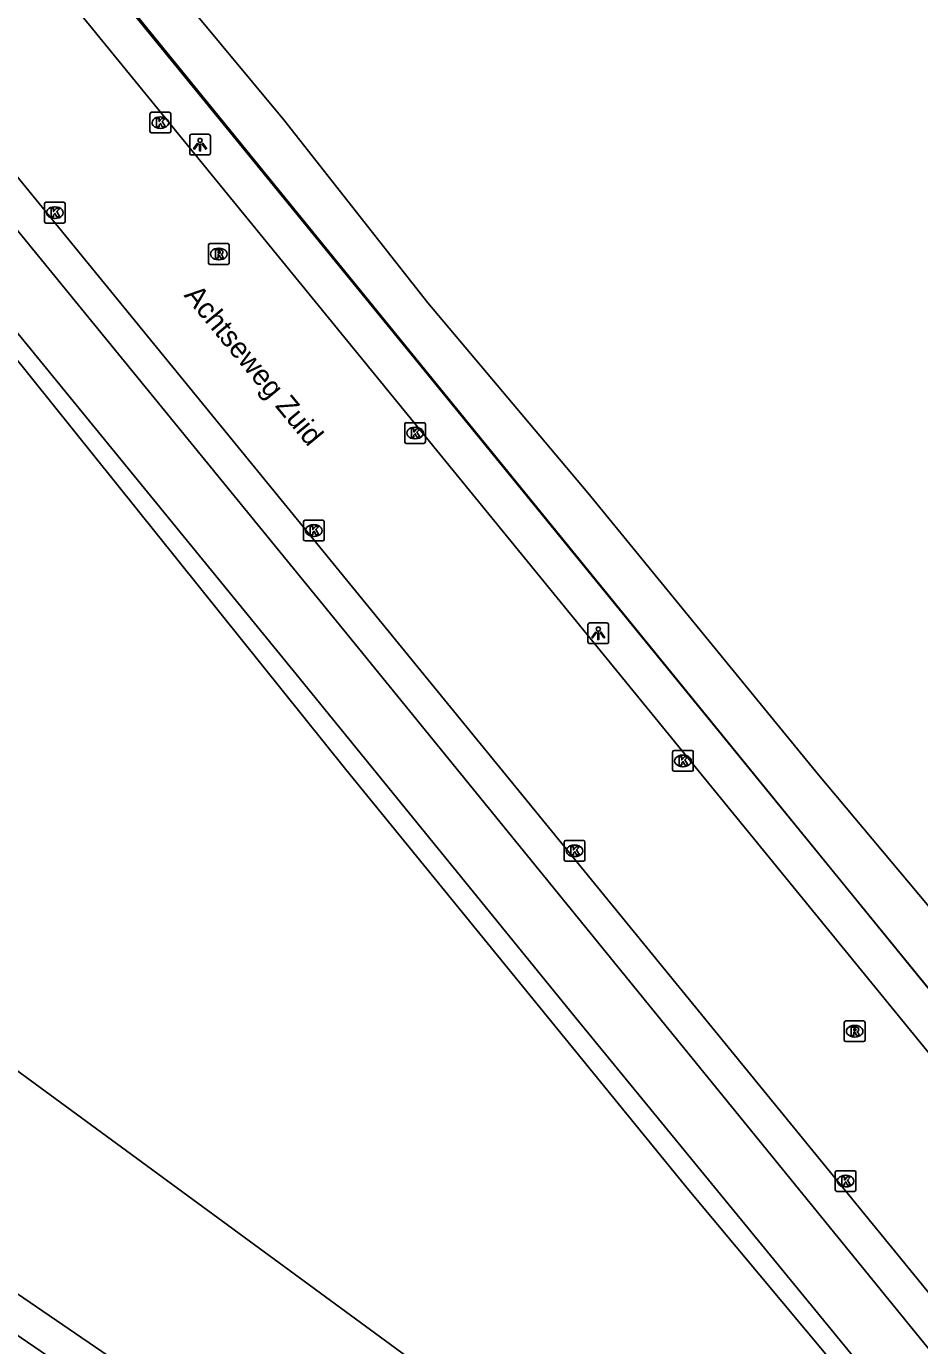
# Model space of a CAD drawing. Extents: x 157154 to 159278, y 385000 to 386650.
# Drawn here: x 158566.6 to 158609.7, y 386048.4 to 386112.1 of the extents above; entities that cross this region are included whole.
import ezdxf

# ---------------------------------------------------------------- set-up
doc = ezdxf.new("R2010")
doc.units = 0
for name, color, linetype in [('IMGEO_Berm_groen', 7, 'Continuous'), ('IMGEO_Fietspad_gesloten', 7, 'Continuous'), ('IMGEO_Gemengd_bos', 7, 'Continuous'), ('IMGEO_Hek', 7, 'Continuous'), ('IMGEO_Kolk', 7, 'Continuous'), ('IMGEO_Lichtpunt', 7, 'Continuous'), ('IMGEO_Openbare_ruimte_label', 7, 'Continuous'), ('IMGEO_Rijbaan_lokaal_open', 7, 'Continuous'), ('IMGEO_Rioolput', 7, 'Continuous'), ('IMGEO_Spoorbaan_halfverhard', 7, 'Continuous')]:
    doc.layers.add(name, color=color, linetype=linetype)

msp = doc.modelspace()

# ---------------------------------------------------------------- linework, layer by layer
at = {"layer": 'IMGEO_Berm_groen'}
msp.add_lwpolyline([(158841.489, 385782.337), (158835.15, 385790.114), (158809.757, 385821.269), (158676.254, 385984.739), (158663.791, 386000), (158641.091, 386027.796), (158568.335, 386116.93)], dxfattribs=at)
at = {"layer": 'IMGEO_Fietspad_gesloten'}
for points in [[(158496.283, 386187.658), (158499.727, 386183.447), (158522.187, 386156.142), (158552.142, 386119.431), (158582.074, 386082.79), (158611.265, 386046.941), (158624.352, 386030.949), (158632.65, 386020.898), (158649.904, 386000), (158653.358, 385995.817), (158682.792, 385959.807), (158711.087, 385925.065), (158740.719, 385888.815), (158770.311, 385852.497), (158799.749, 385816.443), (158822.714, 385788.211), (158826.18, 385783.962)], [(158827.277, 385777.76), (158822.455, 385783.643), (158820.309, 385786.377), (158797.347, 385814.415), (158767.845, 385850.525), (158738.269, 385886.799), (158708.596, 385923.166), (158680.309, 385957.863), (158650.869, 385993.846), (158645.822, 386000), (158630.32, 386018.902), (158593.245, 386064.109), (158579.638, 386080.846), (158549.77, 386117.391), (158519.812, 386154.179), (158500, 386178.402), (158498.839, 386179.679), (158494.054, 386185.565)]]:
    msp.add_lwpolyline(points, dxfattribs=at)
at = {"layer": 'IMGEO_Gemengd_bos'}
for points in [[(158522.421, 386148.754), (158522.797, 386149.273), (158562.792, 386100.195), (158582.034, 386076.24), (158598.59, 386055.948), (158614.423, 386036.988), (158629.667, 386018.342), (158644.664, 386000), (158685.906, 385949.871), (158806.779, 385801.489), (158826.26, 385777.342), (158807.778, 385750), (158754.904, 385671.741), (158747.524, 385671.524)], [(158752.088, 385863.94), (158673.395, 385918.963), (158680.465, 385942.644), (158609.969, 386004.227), (158617.585, 386024.002), (158504.436, 386106.963), (158449.164, 386031.579), (158559.121, 385955.588)]]:
    msp.add_lwpolyline(points, dxfattribs=at)
at = {"layer": 'IMGEO_Hek'}
for points in [[(158629.667, 386018.342), (158614.423, 386036.988), (158598.59, 386055.948), (158582.034, 386076.24), (158562.792, 386100.195), (158522.797, 386149.273), (158522.421, 386148.754)], [(158817.976, 385811.106), (158808.477, 385822.704), (158800.605, 385832.374), (158792.744, 385842.021), (158789.55, 385845.893), (158757.964, 385884.486), (158738.986, 385907.741), (158732.747, 385915.407), (158728.03, 385921.204), (158723.262, 385926.998), (158694.914, 385961.78), (158690.262, 385967.581), (158687.052, 385971.435), (158669.656, 385992.715), (158661.796, 386002.376), (158660.21, 386004.291), (158633.403, 386037.186), (158611.324, 386064.219), (158568.401, 386116.979)]]:
    msp.add_lwpolyline(points, dxfattribs=at)
at = {"layer": 'IMGEO_Kolk'}
for p, q in [((158572.577, 386107.031), (158572.577, 386107.883)), ((158572.652, 386107.957), (158573.504, 386107.957)), ((158573.065, 386107.737), (158573.09, 386107.737)), ((158573.578, 386107.883), (158573.578, 386107.031)), ((158573.504, 386106.957), (158572.652, 386106.957)), ((158573.088, 386107.177), (158573.063, 386107.177)), ((158567.481, 386102.687), (158567.481, 386103.539)), ((158567.556, 386103.613), (158568.408, 386103.613)), ((158567.969, 386103.393), (158567.994, 386103.393)), ((158568.482, 386103.539), (158568.482, 386102.687)), ((158568.408, 386102.613), (158567.556, 386102.613)), ((158567.992, 386102.833), (158567.967, 386102.833)), ((158584.948, 386092.978), (158585.8, 386092.978)), ((158584.873, 386092.052), (158584.873, 386092.904)), ((158585.361, 386092.758), (158585.386, 386092.758)), ((158585.874, 386092.904), (158585.874, 386092.052)), ((158585.8, 386091.978), (158584.948, 386091.978)), ((158585.384, 386092.198), (158585.359, 386092.198)), ((158579.987, 386087.345), (158579.987, 386088.197)), ((158580.062, 386088.271), (158580.914, 386088.271)), ((158580.475, 386088.051), (158580.5, 386088.051)), ((158580.988, 386088.197), (158580.988, 386087.345)), ((158580.914, 386087.271), (158580.062, 386087.271)), ((158580.498, 386087.491), (158580.473, 386087.491)), ((158597.804, 386076.231), (158597.804, 386077.083)), ((158597.879, 386077.157), (158598.731, 386077.157)), ((158598.805, 386077.083), (158598.805, 386076.231)), ((158598.292, 386076.937), (158598.317, 386076.937)), ((158598.731, 386076.157), (158597.879, 386076.157)), ((158598.315, 386076.377), (158598.29, 386076.377)), ((158592.572, 386071.89), (158592.572, 386072.742)), ((158592.647, 386072.816), (158593.499, 386072.816)), ((158593.06, 386072.596), (158593.085, 386072.596)), ((158593.573, 386072.742), (158593.573, 386071.89)), ((158593.083, 386072.036), (158593.058, 386072.036)), ((158593.499, 386071.816), (158592.647, 386071.816)), ((158605.655, 386055.955), (158605.655, 386056.807)), ((158605.73, 386056.881), (158606.582, 386056.881)), ((158606.143, 386056.661), (158606.168, 386056.661)), ((158606.656, 386056.807), (158606.656, 386055.955)), ((158606.166, 386056.101), (158606.141, 386056.101)), ((158606.582, 386055.881), (158605.73, 386055.881))]:
    msp.add_line(p, q, dxfattribs=at)
for points in [[(158572.577, 386107.031), (158572.577, 386107.883)], [(158572.652, 386107.957), (158573.504, 386107.957)], [(158572.898, 386107.657), (158573.021, 386107.657), (158573.021, 386107.506), (158573.151, 386107.657), (158573.315, 386107.657), (158573.169, 386107.506), (158573.322, 386107.257), (158573.17, 386107.257), (158573.085, 386107.421), (158573.021, 386107.354), (158573.021, 386107.257), (158572.898, 386107.257), (158572.898, 386107.657)], [(158573.578, 386107.883), (158573.578, 386107.031)], [(158573.504, 386106.957), (158572.652, 386106.957)], [(158567.481, 386102.687), (158567.481, 386103.539)], [(158567.556, 386103.613), (158568.408, 386103.613)], [(158567.802, 386103.313), (158567.925, 386103.313), (158567.925, 386103.162), (158568.055, 386103.313), (158568.219, 386103.313), (158568.073, 386103.162), (158568.226, 386102.913), (158568.074, 386102.913), (158567.989, 386103.077), (158567.925, 386103.01), (158567.925, 386102.913), (158567.802, 386102.913), (158567.802, 386103.313)], [(158568.482, 386103.539), (158568.482, 386102.687)], [(158568.408, 386102.613), (158567.556, 386102.613)], [(158584.948, 386092.978), (158585.8, 386092.978)], [(158584.873, 386092.052), (158584.873, 386092.904)], [(158585.194, 386092.678), (158585.317, 386092.678), (158585.317, 386092.527), (158585.447, 386092.678), (158585.611, 386092.678), (158585.465, 386092.527), (158585.618, 386092.278), (158585.466, 386092.278), (158585.381, 386092.442), (158585.317, 386092.375), (158585.317, 386092.278), (158585.194, 386092.278), (158585.194, 386092.678)], [(158585.874, 386092.904), (158585.874, 386092.052)], [(158585.8, 386091.978), (158584.948, 386091.978)], [(158579.987, 386087.345), (158579.987, 386088.197)], [(158580.062, 386088.271), (158580.914, 386088.271)], [(158580.308, 386087.971), (158580.431, 386087.971), (158580.431, 386087.82), (158580.561, 386087.971), (158580.725, 386087.971), (158580.579, 386087.82), (158580.732, 386087.571), (158580.58, 386087.571), (158580.495, 386087.735), (158580.431, 386087.668), (158580.431, 386087.571), (158580.308, 386087.571), (158580.308, 386087.971)], [(158580.988, 386088.197), (158580.988, 386087.345)], [(158580.914, 386087.271), (158580.062, 386087.271)], [(158597.804, 386076.231), (158597.804, 386077.083)], [(158597.879, 386077.157), (158598.731, 386077.157)], [(158598.805, 386077.083), (158598.805, 386076.231)], [(158598.125, 386076.857), (158598.248, 386076.857), (158598.248, 386076.706), (158598.378, 386076.857), (158598.542, 386076.857), (158598.396, 386076.706), (158598.549, 386076.457), (158598.397, 386076.457), (158598.312, 386076.621), (158598.248, 386076.554), (158598.248, 386076.457), (158598.125, 386076.457), (158598.125, 386076.857)], [(158598.731, 386076.157), (158597.879, 386076.157)], [(158592.572, 386071.89), (158592.572, 386072.742)], [(158592.647, 386072.816), (158593.499, 386072.816)], [(158593.573, 386072.742), (158593.573, 386071.89)], [(158592.893, 386072.516), (158593.016, 386072.516), (158593.016, 386072.365), (158593.146, 386072.516), (158593.31, 386072.516), (158593.164, 386072.365), (158593.317, 386072.116), (158593.165, 386072.116), (158593.08, 386072.28), (158593.016, 386072.213), (158593.016, 386072.116), (158592.893, 386072.116), (158592.893, 386072.516)], [(158593.499, 386071.816), (158592.647, 386071.816)], [(158605.655, 386055.955), (158605.655, 386056.807)], [(158605.73, 386056.881), (158606.582, 386056.881)], [(158606.656, 386056.807), (158606.656, 386055.955)], [(158605.976, 386056.581), (158606.099, 386056.581), (158606.099, 386056.43), (158606.229, 386056.581), (158606.393, 386056.581), (158606.247, 386056.43), (158606.4, 386056.181), (158606.248, 386056.181), (158606.163, 386056.345), (158606.099, 386056.278), (158606.099, 386056.181), (158605.976, 386056.181), (158605.976, 386056.581)], [(158606.582, 386055.881), (158605.73, 386055.881)]]:
    msp.add_lwpolyline(points, dxfattribs=at)
for centre, start, end in [((158572.654, 386107.881), 91.55205, 178.44795), ((158572.654, 386107.881), 91.55205, 178.44795), ((158573.502, 386107.881), 1.55205, 88.44795), ((158573.502, 386107.881), 1.55205, 88.44795), ((158572.654, 386107.033), 181.55205, 268.44795), ((158572.654, 386107.033), 181.55205, 268.44795), ((158573.502, 386107.033), 271.55205, 358.44795), ((158573.502, 386107.033), 271.55205, 358.44795), ((158567.558, 386103.537), 91.55205, 178.44795), ((158567.558, 386103.537), 91.55205, 178.44795), ((158568.406, 386103.537), 1.55205, 88.44795), ((158568.406, 386103.537), 1.55205, 88.44795), ((158567.558, 386102.689), 181.55205, 268.44795), ((158567.558, 386102.689), 181.55205, 268.44795), ((158568.406, 386102.689), 271.55205, 358.44795), ((158568.406, 386102.689), 271.55205, 358.44795), ((158584.95, 386092.902), 91.55205, 178.44795), ((158584.95, 386092.902), 91.55205, 178.44795), ((158585.798, 386092.902), 1.55205, 88.44795), ((158585.798, 386092.902), 1.55205, 88.44795), ((158584.95, 386092.054), 181.55205, 268.44795), ((158584.95, 386092.054), 181.55205, 268.44795), ((158585.798, 386092.054), 271.55205, 358.44795), ((158585.798, 386092.054), 271.55205, 358.44795), ((158580.064, 386088.195), 91.55205, 178.44795), ((158580.064, 386088.195), 91.55205, 178.44795), ((158580.912, 386088.195), 1.55205, 88.44795), ((158580.912, 386088.195), 1.55205, 88.44795), ((158580.064, 386087.347), 181.55205, 268.44795), ((158580.064, 386087.347), 181.55205, 268.44795), ((158580.912, 386087.347), 271.55205, 358.44795), ((158580.912, 386087.347), 271.55205, 358.44795), ((158597.881, 386077.081), 91.55205, 178.44795), ((158597.881, 386077.081), 91.55205, 178.44795), ((158598.729, 386077.081), 1.55205, 88.44795), ((158598.729, 386077.081), 1.55205, 88.44795), ((158597.881, 386076.233), 181.55205, 268.44795), ((158597.881, 386076.233), 181.55205, 268.44795), ((158598.729, 386076.233), 271.55205, 358.44795), ((158598.729, 386076.233), 271.55205, 358.44795), ((158592.649, 386072.74), 91.55205, 178.44795), ((158592.649, 386072.74), 91.55205, 178.44795), ((158593.497, 386072.74), 1.55205, 88.44795), ((158593.497, 386072.74), 1.55205, 88.44795), ((158592.649, 386071.892), 181.55205, 268.44795), ((158592.649, 386071.892), 181.55205, 268.44795), ((158593.497, 386071.892), 271.55205, 358.44795), ((158593.497, 386071.892), 271.55205, 358.44795), ((158605.732, 386056.805), 91.55205, 178.44795), ((158605.732, 386056.805), 91.55205, 178.44795), ((158606.58, 386056.805), 1.55205, 88.44795), ((158606.58, 386056.805), 1.55205, 88.44795), ((158605.732, 386055.957), 181.55205, 268.44795), ((158605.732, 386055.957), 181.55205, 268.44795), ((158606.58, 386055.957), 271.55205, 358.44795), ((158606.58, 386055.957), 271.55205, 358.44795)]:
    msp.add_arc(centre, 0.0765, start, end, dxfattribs=at)
for centre, major_axis, ratio, start_param, end_param in [((158573.064, 386107.457), (-0.387, 0.002), 0.722429, 4.712389, 7.853982), ((158573.089, 386107.457), (-0.39, 0.002), 0.717154, 1.570796, 4.712389), ((158567.968, 386103.113), (-0.387, 0.002), 0.722429, 4.712389, 7.853982), ((158567.993, 386103.113), (-0.39, 0.002), 0.717154, 1.570796, 4.712389), ((158585.36, 386092.478), (-0.387, 0.002), 0.722429, 4.712389, 7.853982), ((158585.385, 386092.478), (-0.39, 0.002), 0.717154, 1.570796, 4.712389), ((158580.474, 386087.771), (-0.387, 0.002), 0.722429, 4.712389, 7.853982), ((158580.499, 386087.771), (-0.39, 0.002), 0.717154, 1.570796, 4.712389), ((158598.291, 386076.657), (-0.387, 0.002), 0.722429, 4.712389, 7.853982), ((158598.316, 386076.657), (-0.39, 0.002), 0.717154, 1.570796, 4.712389), ((158593.059, 386072.316), (-0.387, 0.002), 0.722429, 4.712389, 7.853982), ((158593.084, 386072.316), (-0.39, 0.002), 0.717154, 1.570796, 4.712389), ((158606.142, 386056.381), (-0.387, 0.002), 0.722429, 4.712389, 7.853982), ((158606.167, 386056.381), (-0.39, 0.002), 0.717154, 1.570796, 4.712389)]:
    msp.add_ellipse(centre, major_axis=major_axis, ratio=ratio, start_param=start_param, end_param=end_param, dxfattribs=at)
at = {"layer": 'IMGEO_Lichtpunt'}
for p, q in [((158574.496, 386106.8), (158574.496, 386105.993)), ((158574.496, 386106.8), (158574.496, 386105.993)), ((158575.398, 386106.895), (158574.59, 386106.895)), ((158575.398, 386106.895), (158574.59, 386106.895)), ((158575.492, 386105.993), (158575.492, 386106.8)), ((158575.492, 386105.993), (158575.492, 386106.8)), ((158574.59, 386105.899), (158575.398, 386105.899)), ((158574.59, 386105.899), (158575.398, 386105.899)), ((158593.719, 386083.218), (158593.719, 386082.411)), ((158593.719, 386083.218), (158593.719, 386082.411)), ((158594.621, 386083.313), (158593.813, 386083.313)), ((158594.621, 386083.313), (158593.813, 386083.313)), ((158594.715, 386082.411), (158594.715, 386083.218)), ((158594.715, 386082.411), (158594.715, 386083.218)), ((158593.813, 386082.317), (158594.621, 386082.317)), ((158593.813, 386082.317), (158594.621, 386082.317))]:
    msp.add_line(p, q, dxfattribs=at)
for points in [[(158574.87, 386106.464), (158574.909, 386106.436), (158574.721, 386106.174), (158574.683, 386106.201), (158574.87, 386106.464)], [(158574.972, 386106.416), (158575.019, 386106.416), (158575.019, 386106.094), (158574.972, 386106.094), (158574.972, 386106.416)], [(158575.082, 386106.436), (158575.12, 386106.463), (158575.307, 386106.201), (158575.268, 386106.173), (158575.082, 386106.436)], [(158594.093, 386082.882), (158594.132, 386082.854), (158593.944, 386082.592), (158593.906, 386082.619), (158594.093, 386082.882)], [(158594.195, 386082.834), (158594.242, 386082.834), (158594.242, 386082.512), (158594.195, 386082.512), (158594.195, 386082.834)], [(158594.305, 386082.854), (158594.343, 386082.881), (158594.53, 386082.619), (158594.491, 386082.591), (158594.305, 386082.854)]]:
    msp.add_lwpolyline(points, dxfattribs=at)
for centre in [(158574.995, 386106.598), (158594.218, 386083.016)]:
    msp.add_circle(centre, 0.0994, dxfattribs=at)
for centre, start, end in [((158574.59, 386106.8), 90, 180), ((158574.59, 386106.8), 90, 180), ((158575.398, 386106.8), 0, 90), ((158575.398, 386106.8), 0, 90), ((158574.59, 386105.993), 180, 270), ((158574.59, 386105.993), 180, 270), ((158575.398, 386105.993), 270, 0), ((158575.398, 386105.993), 270, 360), ((158593.813, 386083.218), 90, 180), ((158593.813, 386083.218), 90, 180), ((158594.621, 386083.218), 0, 90), ((158594.621, 386083.218), 0, 90), ((158593.813, 386082.411), 180, 270), ((158593.813, 386082.411), 180, 270), ((158594.621, 386082.411), 270, 0), ((158594.621, 386082.411), 270, 360)]:
    msp.add_arc(centre, 0.0946, start, end, dxfattribs=at)
at = {"layer": 'IMGEO_Rijbaan_lokaal_open'}
for points in [[(158821.629, 385791.859), (158706.345, 385933.191), (158665.287, 385983.638), (158646.806, 386006.152), (158633.892, 386021.96), (158498.041, 386188.248)], [(158536.019, 386153.315), (158639.597, 386026.539), (158659.828, 386001.777), (158827.274, 385796.539)], [(158528.788, 385896.988), (158530.966, 385900.207), (158532.343, 385900.291), (158532.83, 385901.031), (158532.02, 385901.791), (158547.795, 385924.966), (158558.788, 385940.958), (158561.569, 385944.821), (158563.736, 385957.639), (158567.635, 385963.317), (158607.837, 386022.47), (158512.758, 386087.437), (158468.56, 386022.832), (158553.362, 385964.68), (158559.766, 385960.279), (158559.121, 385955.588)], [(158470.715, 386023.283), (158513.114, 386085.174), (158605.625, 386022.008), (158566.189, 385964.23), (158563.362, 385960.073), (158554.354, 385966.159), (158470.715, 386023.283)]]:
    msp.add_lwpolyline(points, dxfattribs=at)
at = {"layer": 'IMGEO_Rioolput'}
for p, q in [((158575.4, 386100.691), (158575.4, 386101.543)), ((158575.475, 386101.617), (158576.327, 386101.617)), ((158575.888, 386101.397), (158575.913, 386101.397)), ((158576.401, 386101.543), (158576.401, 386100.691)), ((158576.327, 386100.617), (158575.475, 386100.617)), ((158575.911, 386100.837), (158575.886, 386100.837)), ((158606.093, 386063.185), (158606.093, 386064.037)), ((158606.168, 386064.111), (158607.02, 386064.111)), ((158606.581, 386063.891), (158606.606, 386063.891)), ((158607.094, 386064.037), (158607.094, 386063.185)), ((158607.02, 386063.111), (158606.168, 386063.111)), ((158606.604, 386063.331), (158606.579, 386063.331))]:
    msp.add_line(p, q, dxfattribs=at)
for points in [[(158575.4, 386100.691), (158575.4, 386101.543)], [(158575.475, 386101.617), (158576.327, 386101.617)], [(158575.989, 386101.315), (158575.737, 386101.317), (158575.737, 386100.917)], [(158575.915, 386101.236), (158575.861, 386101.236), (158575.861, 386101.155)], [(158576.401, 386101.543), (158576.401, 386100.691)], [(158576.327, 386100.617), (158575.475, 386100.617)], [(158575.737, 386100.917), (158575.861, 386100.917), (158575.861, 386101.079), (158575.872, 386101.079)], [(158575.861, 386101.155), (158575.913, 386101.155)], [(158575.919, 386101.05), (158575.99, 386100.917), (158576.13, 386100.917), (158576.065, 386101.043)], [(158606.093, 386063.185), (158606.093, 386064.037)], [(158606.168, 386064.111), (158607.02, 386064.111)], [(158606.682, 386063.809), (158606.43, 386063.811), (158606.43, 386063.411)], [(158606.608, 386063.73), (158606.554, 386063.73), (158606.554, 386063.649)], [(158607.094, 386064.037), (158607.094, 386063.185)], [(158607.02, 386063.111), (158606.168, 386063.111)], [(158606.43, 386063.411), (158606.554, 386063.411), (158606.554, 386063.573), (158606.565, 386063.573)], [(158606.554, 386063.649), (158606.606, 386063.649)], [(158606.612, 386063.544), (158606.683, 386063.411), (158606.823, 386063.411), (158606.758, 386063.537)]]:
    msp.add_lwpolyline(points, dxfattribs=at)
for centre, radius, start, end in [((158575.477, 386101.541), 0.0765, 91.55205, 178.44795), ((158575.477, 386101.541), 0.0765, 91.55205, 178.44795), ((158575.921, 386101.14), 0.0964, 77.00612, 93.18647), ((158575.935, 386101.197), 0.0378, 276.66336, 79.67722), ((158575.988, 386101.205), 0.109, 350.36119, 89.41601), ((158576.325, 386101.541), 0.0765, 1.55205, 88.44795), ((158576.325, 386101.541), 0.0765, 1.55205, 88.44795), ((158575.477, 386100.693), 0.0765, 181.55205, 268.44795), ((158575.477, 386100.693), 0.0765, 181.55205, 268.44795), ((158575.871, 386101.026), 0.0533, 26.02933, 88.69889), ((158575.897, 386101.344), 0.19, 274.7715, 282.96867), ((158575.986, 386101.205), 0.112, 277.58423, 350.98172), ((158575.97, 386100.99), 0.108, 29.51342, 73.79051), ((158576.325, 386100.693), 0.0765, 271.55205, 358.44795), ((158576.325, 386100.693), 0.0765, 271.55205, 358.44795), ((158606.17, 386064.035), 0.0765, 91.55205, 178.44795), ((158606.17, 386064.035), 0.0765, 91.55205, 178.44795), ((158606.614, 386063.634), 0.0964, 77.00612, 93.18647), ((158606.628, 386063.691), 0.0378, 276.66336, 79.67722), ((158606.681, 386063.699), 0.109, 350.36119, 89.41601), ((158606.679, 386063.699), 0.112, 277.58423, 350.98172), ((158607.018, 386064.035), 0.0765, 1.55205, 88.44795), ((158607.018, 386064.035), 0.0765, 1.55205, 88.44795), ((158606.17, 386063.187), 0.0765, 181.55205, 268.44795), ((158606.17, 386063.187), 0.0765, 181.55205, 268.44795), ((158606.564, 386063.52), 0.0533, 26.02933, 88.69889), ((158606.59, 386063.838), 0.19, 274.7715, 282.96867), ((158606.663, 386063.484), 0.108, 29.51342, 73.79051), ((158607.018, 386063.187), 0.0765, 271.55205, 358.44795), ((158607.018, 386063.187), 0.0765, 271.55205, 358.44795)]:
    msp.add_arc(centre, radius, start, end, dxfattribs=at)
for centre, major_axis, ratio, start_param, end_param in [((158575.887, 386101.117), (-0.387, 0.002), 0.722429, 4.712389, 7.853982), ((158575.912, 386101.117), (-0.39, 0.002), 0.717154, 1.570796, 4.712389), ((158606.58, 386063.611), (-0.387, 0.002), 0.722429, 4.712389, 7.853982), ((158606.605, 386063.611), (-0.39, 0.002), 0.717154, 1.570796, 4.712389)]:
    msp.add_ellipse(centre, major_axis=major_axis, ratio=ratio, start_param=start_param, end_param=end_param, dxfattribs=at)
at = {"layer": 'IMGEO_Spoorbaan_halfverhard'}
msp.add_lwpolyline([(158539.004, 386155.645), (158551.223, 386140.801), (158563.891, 386125.785), (158579.038, 386107.589), (158585.995, 386098.767), (158593.705, 386089.591), (158604.841, 386075.981), (158612.287, 386067.119), (158630.237, 386045.448), (158637.03, 386036.964), (158663.463, 386005.216), (158671.744, 385994.913), (158680.709, 385984.692), (158688.421, 385975.364), (158694.021, 385968.581), (158700.961, 385959.859), (158733.183, 385920.595), (158751.735, 385898.407), (158775.523, 385869.582), (158795.823, 385845.315), (158809.961, 385828.171), (158813.558, 385823.456), (158818.967, 385817.08), (158842.26, 385789.002)], dxfattribs=at)

# ---------------------------------------------------------------- texts
at = {"layer": 'IMGEO_Openbare_ruimte_label'}
msp.add_text('Achtseweg Zuid', height=1, rotation=309.56351, dxfattribs=at).set_placement((158574.184, 386099.108))

doc.saveas('drawing.dxf')
